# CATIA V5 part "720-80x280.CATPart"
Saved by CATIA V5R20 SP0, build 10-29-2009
Part number: 720-80x280
Definition: NONE
Nomenclature: 720-80x280
Source: Unknown
Description: 720-80x280
Bounding box of the stored display mesh (mm): x 0 to 280, y -40 to 40, z -40 to 40
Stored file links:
  C:\Users\Utente\Desktop\IO LAVORO\3D X SITO CF\X SITO\720\720-80x280.CATPart

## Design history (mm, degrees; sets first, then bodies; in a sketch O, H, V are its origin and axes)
Body1 "720-80x280" (main body)
  Solid1: solid without history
